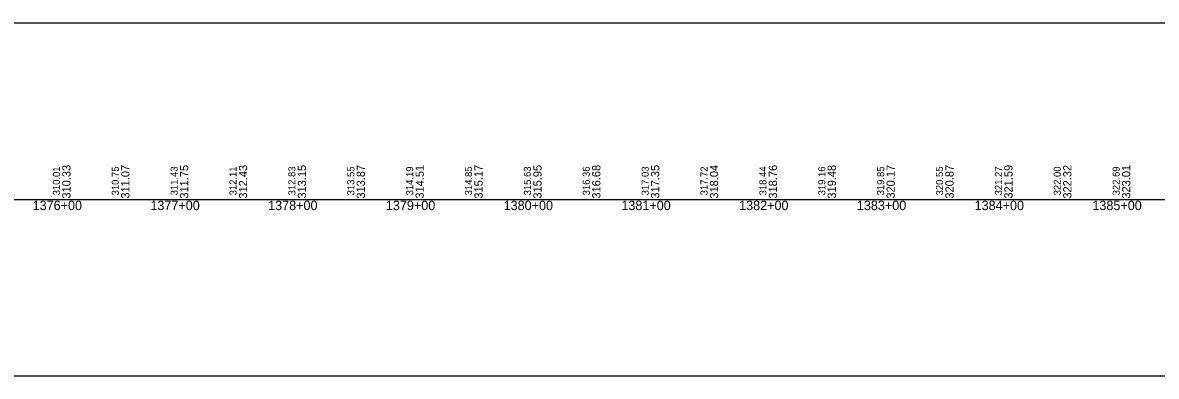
# Model space of a CAD drawing. Extents: x 2898 to 49495, y -15038 to -13538.
# Drawn here: x 27021 to 27983, y -15038 to -14738 of the extents above; entities that cross this region are included whole.
import ezdxf

# ---------------------------------------------------------------- set-up
doc = ezdxf.new("R2010")
doc.units = 0
for name, color, linetype in [('RD_DDB_StaTX', 7, 'Continuous'), ('RD_DDB_StripGrade', 7, 'Continuous'), ('RD_GPK_Profile_Cell', 7, 'Continuous'), ('RD_SHT_ShtClip', 7, 'Continuous')]:
    doc.layers.add(name, color=color, linetype=linetype)

msp = doc.modelspace()

# ---------------------------------------------------------------- linework, layer by layer
at = {"layer": 'RD_GPK_Profile_Cell'}
msp.add_line((2976.05, -14888.47), (48721.13, -14888.47), dxfattribs=at)
at = {"layer": 'RD_SHT_ShtClip'}
msp.add_lwpolyline([(26955.38, -14738.47), (28495.38, -14738.47), (28495.38, -15038.47), (26955.38, -15038.47)], close=True, dxfattribs=at)

# ---------------------------------------------------------------- texts
at = {"layer": 'RD_DDB_StaTX'}
for s, p in [('1376+00', (27029.18, -14897.47)), ('1377+00', (27129.18, -14897.47)), ('1378+00', (27229.18, -14897.47)), ('1379+00', (27329.18, -14897.47)), ('1380+00', (27429.18, -14897.47)), ('1381+00', (27529.18, -14897.47)), ('1382+00', (27629.18, -14897.47)), ('1383+00', (27729.18, -14897.47)), ('1384+00', (27829.18, -14897.47)), ('1385+00', (27929.18, -14897.47))]:
    msp.add_text(s, height=8, dxfattribs=at).set_placement(p)
at = {"layer": 'RD_DDB_StripGrade'}
for s, height, p in [('310.01', 6, (27052.38, -14884.98)), ('310.33', 7, (27061.38, -14887.72)), ('310.75', 6, (27102.38, -14884.98)), ('311.07', 7, (27111.38, -14887.72)), ('311.43', 6, (27152.38, -14884.98)), ('311.75', 7, (27161.38, -14887.72)), ('312.11', 6, (27202.38, -14884.98)), ('312.43', 7, (27211.38, -14887.72)), ('312.83', 6, (27252.38, -14884.98)), ('313.15', 7, (27261.38, -14887.72)), ('313.55', 6, (27302.38, -14884.98)), ('313.87', 7, (27311.38, -14887.72)), ('314.19', 6, (27352.38, -14884.98)), ('314.51', 7, (27361.38, -14887.72)), ('314.85', 6, (27402.38, -14884.98)), ('315.17', 7, (27411.38, -14887.72)), ('315.63', 6, (27452.38, -14884.98)), ('315.95', 7, (27461.38, -14887.72)), ('316.36', 6, (27502.38, -14884.98)), ('316.68', 7, (27511.38, -14887.72)), ('317.03', 6, (27552.38, -14884.98)), ('317.35', 7, (27561.38, -14887.72)), ('317.72', 6, (27602.38, -14884.98)), ('318.04', 7, (27611.38, -14887.72)), ('318.44', 6, (27652.38, -14884.98)), ('318.76', 7, (27661.38, -14887.72)), ('319.16', 6, (27702.38, -14884.98)), ('319.48', 7, (27711.38, -14887.72)), ('319.85', 6, (27752.38, -14884.98)), ('320.17', 7, (27761.38, -14887.72)), ('320.55', 6, (27802.38, -14884.98)), ('320.87', 7, (27811.38, -14887.72)), ('321.27', 6, (27852.38, -14884.98)), ('321.59', 7, (27861.38, -14887.72)), ('322.00', 6, (27902.38, -14884.98)), ('322.32', 7, (27911.38, -14887.72)), ('322.69', 6, (27952.38, -14884.98)), ('323.01', 7, (27961.38, -14887.72))]:
    msp.add_text(s, height=height, rotation=90, dxfattribs=at).set_placement(p)

doc.saveas('drawing.dxf')
